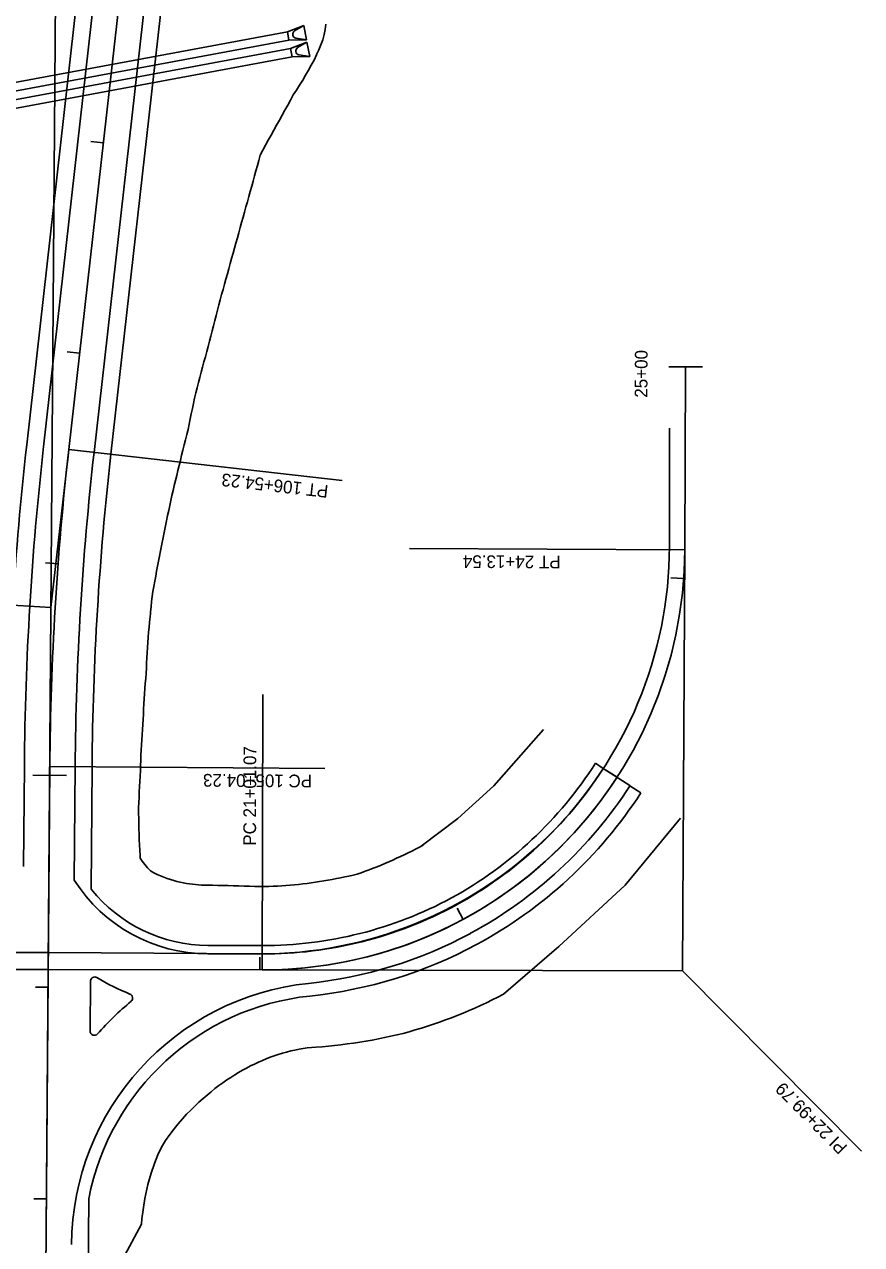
# Model space of a CAD drawing. Extents: x 1311167 to 1314552, y 2087587 to 2090602.
# Drawn here: x 1313980 to 1314376, y 2088279 to 2088855 of the extents above; entities that cross this region are included whole.
import ezdxf

# ---------------------------------------------------------------- set-up
doc = ezdxf.new("R2010")
doc.units = 0
for name, color, linetype in [('R_Bridge', 7, 'Continuous'), ('R_Guardrail', 7, 'Continuous'), ('R_Horz Alg Stationing', 7, 'Continuous'), ('R_Proposed Road', 7, 'Continuous'), ('R_Shld_GR', 7, 'Continuous'), ('R_Shoulder', 7, 'Continuous'), ('S_EDGE_BITUMINOUS', 7, 'Continuous'), ('S_EDGE_CONCRETE', 7, 'Continuous'), ('S_EDGE_PAVEMENT', 7, 'Continuous'), ('S_PAVEMENT_CROWN', 7, 'Continuous')]:
    doc.layers.add(name, color=color, linetype=linetype)

msp = doc.modelspace()

# ---------------------------------------------------------------- linework, layer by layer
at = {"layer": 'R_Bridge'}
for points in [[(1314011.54, 2088800.1), (1314017.5, 2088799.43)], [(1314000.33, 2088700.73), (1314006.29, 2088700.06)], [(1313990.12, 2088601.03), (1313996.1, 2088600.59)], [(1313984.14, 2088500.75), (1314000.14, 2088500.62)], [(1313985.38, 2088400.73), (1313991.38, 2088400.69)], [(1313984.61, 2088300.74), (1313990.61, 2088300.69)]]:
    msp.add_lwpolyline(points, dxfattribs=at)
at = {"layer": 'R_Guardrail'}
for points in [[(1313992.17, 2088504.92), (1313992.74, 2088579.98), (1314001.16, 2088654.58)], [(1314001.16, 2088654.58), (1314130.34, 2088640)], [(1313992.74, 2088579.98), (1313872.96, 2088587.18)], [(1313992.17, 2088504.92), (1314122.17, 2088503.92)]]:
    msp.add_lwpolyline(points, dxfattribs=at)
at = {"layer": 'R_Horz Alg Stationing'}
for p, q in [((1313988.32, 2088000.7), (1313997.14, 2089155.24)), ((1314284.97, 2088608.82), (1314285.06, 2088664.6)), ((1313889.89, 2088417.38), (1313991.5, 2088416.97)), ((1313991.5, 2088416.97), (1314091.16, 2088416.4))]:
    msp.add_line(p, q, dxfattribs=at)
msp.add_arc((1314092.24, 2088609.13), 192.73, 269.67706, 359.90767, dxfattribs=at)
at = {"layer": 'R_Proposed Road'}
for p, q in [((1314001.16, 2088654.58), (1314052.57, 2089110.2)), ((1314001.16, 2088654.58), (1314052.57, 2089110.2)), ((1314001.16, 2088654.58), (1314052.57, 2089110.2)), ((1314292.21, 2088607.13), (1314292.63, 2088693.59)), ((1314292.21, 2088607.13), (1314292.63, 2088693.59)), ((1313988.32, 2088000.7), (1313992.17, 2088504.92)), ((1313992.14, 2088501.05), (1313992.17, 2088504.92)), ((1313896.44, 2088409.22), (1313991.44, 2088409.03)), ((1313896.44, 2088409.22), (1313991.44, 2088409.03)), ((1313991.44, 2088409.03), (1314092.51, 2088408.82)), ((1313991.44, 2088409.03), (1314092.51, 2088408.82))]:
    msp.add_line(p, q, dxfattribs=at)
for centre, radius, start, end in [((1315424.52, 2088493.98), 1432.39, 173.5625, 179.5625), ((1315424.52, 2088493.98), 1432.39, 173.5625, 179.5625), ((1315424.52, 2088493.98), 1432.39, 173.5625, 179.5625), ((1314092.92, 2088608.11), 199.29, 269.88333, 359.71667), ((1314092.92, 2088608.11), 199.29, 269.88333, 327.0745)]:
    msp.add_arc(centre, radius, start, end, dxfattribs=at)
at = {"layer": 'R_Shld_GR'}
for points in [[(1314092.51, 2088408.82), (1314291.22, 2088408.42), (1314292.21, 2088607.13)], [(1314292.21, 2088607.13), (1314162.21, 2088607.77)], [(1314092.51, 2088408.82), (1314092.78, 2088538.82)], [(1314291.22, 2088408.42), (1314375.78, 2088323.27)]]:
    msp.add_lwpolyline(points, dxfattribs=at)
at = {"layer": 'R_Shoulder'}
for points in [[(1314284.63, 2088693.63), (1314300.63, 2088693.55)], [(1314285.7, 2088594.04), (1314291.68, 2088593.6)], [(1314255.16, 2088503.05), (1314260.2, 2088499.79)], [(1314184.63, 2088437.97), (1314187.47, 2088432.68)], [(1314091.45, 2088414.83), (1314091.44, 2088408.83)]]:
    msp.add_lwpolyline(points, dxfattribs=at)
at = {"layer": 'S_EDGE_BITUMINOUS'}
for p, q in [((1314104.47, 2088851.9), (1314112.23, 2088854.88)), ((1314107.82, 2088852.24), (1314112.23, 2088854.88)), ((1314113.51, 2088847.99), (1314112.23, 2088854.88)), ((1313926.54, 2088818.73), (1314104.47, 2088851.9)), ((1314105.2, 2088847.97), (1314104.47, 2088851.9)), ((1313927.27, 2088814.79), (1314105.2, 2088847.97)), ((1313928, 2088810.86), (1314105.94, 2088844.04)), ((1314105.2, 2088847.97), (1314113.51, 2088847.99)), ((1314105.94, 2088844.04), (1314113.69, 2088847.01)), ((1314106.67, 2088840.11), (1314105.94, 2088844.04)), ((1314108.46, 2088848.86), (1314113.51, 2088847.99)), ((1314109.29, 2088844.38), (1314113.69, 2088847.01)), ((1314114.98, 2088840.13), (1314113.69, 2088847.01)), ((1313928.74, 2088806.93), (1314106.67, 2088840.11)), ((1314106.67, 2088840.11), (1314114.98, 2088840.13)), ((1314109.92, 2088841), (1314114.98, 2088840.13))]:
    msp.add_line(p, q, dxfattribs=at)
for centre in [(1314108.77, 2088850.67), (1314110.24, 2088842.81)]:
    msp.add_arc(centre, 1.83, 120.88099, 260.24384, dxfattribs=at)
at = {"layer": 'S_EDGE_CONCRETE'}
msp.add_line((1314035.5, 2088288.69), (1314027.56, 2088274.13), dxfattribs=at)
for points in [[(1314122.61, 2088855.5), (1314122.36, 2088853.01), (1314121.75, 2088850.56), (1314121.18, 2088848.11), (1314120.21, 2088845.7), (1314119.23, 2088843.3), (1314118.43, 2088841.38), (1314118.23, 2088840.9), (1314117.08, 2088838.51), (1314115.71, 2088836.15), (1314114.38, 2088833.78), (1314113.05, 2088831.42), (1314111.68, 2088829.06), (1314110.19, 2088826.71), (1314108.7, 2088824.36), (1314107.21, 2088822.01), (1314105.9, 2088819.64), (1314104.59, 2088817.28), (1314103.27, 2088814.91), (1314101.96, 2088812.54), (1314100.65, 2088810.17), (1314099.35, 2088807.8), (1314098.04, 2088805.44), (1314096.73, 2088803.07), (1314095.43, 2088800.7), (1314094.29, 2088798.61), (1314094.13, 2088798.33), (1314092.83, 2088795.96), (1314091.65, 2088793.58), (1314090.95, 2088791.14), (1314090.27, 2088788.7), (1314089.6, 2088786.26), (1314088.93, 2088783.82), (1314088.26, 2088781.38), (1314087.58, 2088778.94), (1314086.89, 2088776.5), (1314086.21, 2088774.06), (1314085.54, 2088771.62), (1314084.86, 2088769.18), (1314084.19, 2088766.74), (1314083.52, 2088764.3), (1314082.84, 2088761.87), (1314082.16, 2088759.43), (1314081.49, 2088756.99), (1314080.81, 2088754.55), (1314080.14, 2088752.11), (1314079.46, 2088749.67), (1314078.79, 2088747.23), (1314078.11, 2088744.79), (1314077.43, 2088742.35), (1314076.76, 2088739.91), (1314076.08, 2088737.47), (1314075.41, 2088735.03), (1314074.73, 2088732.59), (1314074.03, 2088730.15), (1314073.33, 2088727.72), (1314072.69, 2088725.27), (1314072.04, 2088722.83), (1314071.4, 2088720.39), (1314070.75, 2088717.94), (1314070.12, 2088715.5), (1314069.48, 2088713.06), (1314068.85, 2088710.61), (1314068.22, 2088708.17), (1314067.58, 2088705.72), (1314066.95, 2088703.28), (1314066.31, 2088700.83), (1314065.68, 2088698.39), (1314065.04, 2088695.95), (1314064.41, 2088693.5), (1314063.77, 2088691.06), (1314063.14, 2088688.61), (1314062.51, 2088686.17), (1314061.87, 2088683.72), (1314061.24, 2088681.28), (1314060.6, 2088678.84), (1314060.05, 2088676.38), (1314059.55, 2088673.92), (1314059.05, 2088671.46), (1314058.55, 2088669), (1314058.05, 2088666.54), (1314057.5, 2088664.09), (1314056.87, 2088661.65), (1314056.24, 2088659.2), (1314055.62, 2088656.75), (1314055.04, 2088654.3), (1314054.45, 2088651.85), (1314053.87, 2088649.4), (1314053.3, 2088647.02), (1314052.74, 2088644.66), (1314052.18, 2088642.29), (1314051.59, 2088639.93), (1314051.01, 2088637.57), (1314050.45, 2088635.21), (1314049.92, 2088632.84), (1314049.4, 2088630.47), (1314048.88, 2088628.09), (1314048.36, 2088625.72), (1314047.86, 2088623.34), (1314047.35, 2088620.97), (1314046.86, 2088618.59), (1314046.36, 2088616.21), (1314045.88, 2088613.83), (1314045.4, 2088611.44), (1314044.92, 2088609.06), (1314044.45, 2088606.67), (1314043.99, 2088604.28), (1314043.53, 2088601.9), (1314043.08, 2088599.51), (1314042.63, 2088597.11), (1314042.22, 2088594.72), (1314041.78, 2088592.33), (1314041.34, 2088589.93), (1314040.9, 2088587.53), (1314040.58, 2088585.13), (1314040.31, 2088582.72), (1314040.04, 2088580.31), (1314039.78, 2088577.9), (1314039.7, 2088577.16), (1314039.54, 2088575.49), (1314039.31, 2088573.08), (1314039.09, 2088570.67), (1314038.87, 2088568.25), (1314038.68, 2088565.84), (1314038.52, 2088563.42), (1314038.37, 2088561), (1314038.22, 2088558.59), (1314038.08, 2088556.17), (1314037.94, 2088553.75), (1314037.8, 2088551.33), (1314037.67, 2088548.91), (1314037.49, 2088546.49), (1314037.3, 2088544.08), (1314037.12, 2088541.66), (1314036.94, 2088539.24), (1314036.76, 2088536.82), (1314036.64, 2088534.4), (1314036.52, 2088531.98), (1314036.41, 2088529.56), (1314036.31, 2088527.14), (1314036.18, 2088524.72), (1314036.02, 2088522.29), (1314035.86, 2088519.87), (1314035.71, 2088517.45), (1314035.56, 2088515.03), (1314035.41, 2088512.61), (1314035.27, 2088510.18), (1314035.15, 2088507.76), (1314035.07, 2088505.33), (1314035, 2088502.86), (1314034.87, 2088500.36), (1314034.73, 2088497.86), (1314034.6, 2088495.36), (1314034.46, 2088492.86), (1314034.33, 2088490.36), (1314034.2, 2088487.86), (1314034.07, 2088485.36)], [(1314167.68, 2088467.3), (1314185.05, 2088480.27), (1314202.04, 2088495.78), (1314225.41, 2088522.31)], [(1314034.89, 2088461.56), (1314034.8, 2088462.86), (1314034.69, 2088465.36), (1314034.58, 2088467.86), (1314034.47, 2088470.36), (1314034.36, 2088472.86), (1314034.28, 2088475.36), (1314034.27, 2088477.86), (1314034.24, 2088480.36), (1314034.12, 2088482.86), (1314034.07, 2088485.36)], [(1314290.13, 2088480.41), (1314264.03, 2088448.82), (1314232.76, 2088419.88), (1314206.53, 2088397.34)], [(1314039.74, 2088455.67), (1314041.35, 2088454.73), (1314042.97, 2088453.93), (1314044.56, 2088453.2), (1314046.13, 2088452.55), (1314047.69, 2088451.97), (1314049.22, 2088451.45), (1314050.74, 2088450.98), (1314052.25, 2088450.58), (1314053.74, 2088450.23), (1314055.23, 2088449.93), (1314056.7, 2088449.69), (1314058.15, 2088449.45), (1314059.59, 2088449.26), (1314061.03, 2088449.12), (1314062.46, 2088448.98), (1314063.88, 2088448.88), (1314065.3, 2088448.81), (1314066.72, 2088448.8), (1314069.02, 2088448.76), (1314071.52, 2088448.7), (1314074.02, 2088448.64), (1314076.52, 2088448.67), (1314079.02, 2088448.59), (1314081.52, 2088448.5), (1314084.02, 2088448.41), (1314086.52, 2088448.32), (1314089.02, 2088448.22), (1314091.52, 2088448.16), (1314093.74, 2088448.19), (1314095.74, 2088448.25), (1314097.75, 2088448.33), (1314099.75, 2088448.42), (1314101.75, 2088448.53), (1314103.75, 2088448.67), (1314105.75, 2088448.82), (1314107.75, 2088448.99), (1314109.74, 2088449.18), (1314111.74, 2088449.39), (1314113.73, 2088449.63), (1314115.71, 2088449.92), (1314117.7, 2088450.22), (1314119.68, 2088450.54), (1314121.66, 2088450.85), (1314123.63, 2088451.19), (1314125.61, 2088451.54), (1314127.58, 2088451.91), (1314129.55, 2088452.3), (1314131.52, 2088452.71), (1314133.49, 2088453.13), (1314135.45, 2088453.58), (1314137.4, 2088454.07), (1314139.31, 2088454.7), (1314141.2, 2088455.38), (1314143.08, 2088456.09), (1314144.96, 2088456.81), (1314146.82, 2088457.56), (1314148.68, 2088458.32), (1314150.53, 2088459.09), (1314152.37, 2088459.89), (1314154.2, 2088460.7), (1314156.02, 2088461.54), (1314157.85, 2088462.36), (1314159.67, 2088463.2), (1314161.48, 2088464.05), (1314163.27, 2088464.94), (1314165.04, 2088465.87), (1314166.81, 2088466.82), (1314168.56, 2088467.78)], [(1314034.89, 2088461.56), (1314035.84, 2088460.2), (1314037.11, 2088458.57), (1314038.38, 2088457.03), (1314039.74, 2088455.67)], [(1314046.85, 2088328.27), (1314048.89, 2088331.11), (1314050.91, 2088333.74), (1314052.91, 2088336.18), (1314054.88, 2088338.47), (1314056.85, 2088340.6), (1314058.81, 2088342.61), (1314060.74, 2088344.52), (1314062.66, 2088346.33), (1314064.57, 2088348.05), (1314066.46, 2088349.68), (1314068.35, 2088351.24), (1314070.23, 2088352.73), (1314072.09, 2088354.16), (1314073.96, 2088355.52), (1314075.83, 2088356.82), (1314077.69, 2088358.06), (1314079.55, 2088359.24), (1314081.41, 2088360.37), (1314083.28, 2088361.44), (1314085.14, 2088362.46), (1314087.01, 2088363.43), (1314088.87, 2088364.35), (1314090.74, 2088365.24), (1314092.61, 2088366.07), (1314094.48, 2088366.85), (1314096.36, 2088367.57), (1314098.24, 2088368.25), (1314100.13, 2088368.88), (1314102.07, 2088369.48), (1314104.05, 2088370.03), (1314106.02, 2088370.53), (1314107.98, 2088370.98), (1314109.94, 2088371.36), (1314111.9, 2088371.68), (1314113.86, 2088371.94), (1314115.82, 2088372.15), (1314117.88, 2088372.31), (1314120.85, 2088372.53), (1314123.82, 2088372.8), (1314126.78, 2088373.11), (1314129.74, 2088373.46), (1314132.7, 2088373.82), (1314135.66, 2088374.23), (1314138.61, 2088374.67), (1314141.56, 2088375.15), (1314144.5, 2088375.69), (1314147.43, 2088376.25), (1314150.37, 2088376.84), (1314153.29, 2088377.47), (1314156.21, 2088378.14), (1314159.12, 2088378.85), (1314162.01, 2088379.64), (1314164.88, 2088380.47), (1314167.75, 2088381.33), (1314170.61, 2088382.24), (1314173.46, 2088383.17), (1314176.29, 2088384.15), (1314179.12, 2088385.16), (1314181.92, 2088386.21), (1314184.72, 2088387.3), (1314187.5, 2088388.42), (1314190.27, 2088389.58), (1314193.02, 2088390.78), (1314195.75, 2088392.02), (1314198.47, 2088393.3), (1314201.17, 2088394.61), (1314203.86, 2088395.95), (1314206.53, 2088397.34)], [(1314035.5, 2088288.69), (1314035.67, 2088291.28), (1314037.07, 2088300.9), (1314038.48, 2088307.51), (1314040.04, 2088312.83), (1314041.58, 2088317.41), (1314043.25, 2088321.43), (1314044.97, 2088325.05), (1314046.85, 2088328.27)]]:
    msp.add_lwpolyline(points, dxfattribs=at)
at = {"layer": 'S_EDGE_PAVEMENT'}
for p, q in [((1313981.29, 2088656.82), (1314032.69, 2089112.44)), ((1314021.03, 2088652.34), (1314072.44, 2089107.95)), ((1314011.73, 2088446.9), (1314012.17, 2088504.76)), ((1314250.01, 2088506.39), (1314253.73, 2088503.98)), ((1314266.33, 2088495.82), (1314271.49, 2088492.48)), ((1314066.93, 2088420.38), (1314092.54, 2088420.32)), ((1314009.96, 2088215.54), (1314010.61, 2088300.74))]:
    msp.add_line(p, q, dxfattribs=at)
for centre, radius, start, end in [((1315424.52, 2088493.98), 1452.39, 173.5625, 179.5625), ((1315424.52, 2088493.98), 1412.39, 173.5625, 179.5625), ((1314091.75, 2088607.48), 187.79, 298.73164, 327.43214), ((1314092.84, 2088608.07), 212.79, 298.34924, 327.09619), ((1314067.07, 2088491.38), 71, 218.78938, 269.88333), ((1314092.92, 2088608.11), 187.79, 269.88333, 298.3245), ((1314092.92, 2088608.11), 212.79, 275.97277, 298.3245), ((1314127.44, 2088278.12), 119, 95.97277, 169.04314)]:
    msp.add_arc(centre, radius, start, end, dxfattribs=at)
at = {"layer": 'S_PAVEMENT_CROWN'}
for p, q in [((1313989.24, 2088655.92), (1314040.64, 2089111.54)), ((1313989.24, 2088655.92), (1314040.64, 2089111.54)), ((1314013.09, 2088653.23), (1314064.49, 2089108.85)), ((1314013.09, 2088653.23), (1314064.49, 2089108.85)), ((1313979.81, 2088457.6), (1313980.17, 2088505.01)), ((1314003.76, 2088451.16), (1314004.17, 2088504.83)), ((1314253.73, 2088503.98), (1314266.32, 2088495.83)), ((1314066.92, 2088416.38), (1314092.53, 2088416.32)), ((1314011.22, 2088379.93), (1314011.4, 2088403.48))]:
    msp.add_line(p, q, dxfattribs=at)
for centre, radius, start, end in [((1315424.52, 2088493.98), 1444.39, 173.5625, 179.5625), ((1315424.52, 2088493.98), 1444.39, 173.5625, 179.5625), ((1315424.52, 2088493.98), 1420.39, 173.5625, 179.5625), ((1315424.52, 2088493.98), 1420.39, 173.5625, 179.5625), ((1314092.56, 2088607.92), 191.79, 298.44752, 327.19752), ((1314092.56, 2088607.92), 206.79, 298.43857, 327.18857), ((1314067.07, 2088491.38), 75, 212.42238, 269.88333), ((1314092.92, 2088608.11), 191.79, 269.88333, 298.3245), ((1314092.92, 2088608.11), 206.79, 275.97277, 298.3245), ((1314013.4, 2088403.47), 2, 58.59424, 179.5625), ((1314067.07, 2088491.38), 101, 238.59424, 248.5128), ((1314127.44, 2088278.12), 125, 95.97277, 179.5625), ((1314127.44, 2088278.12), 151, 129.88041, 138.29462), ((1314029.34, 2088395.53), 2, 309.88041, 68.5128), ((1314013.22, 2088379.92), 2, 179.5625, 318.29462)]:
    msp.add_arc(centre, radius, start, end, dxfattribs=at)

# ---------------------------------------------------------------- texts
at = {"layer": 'R_Guardrail'}
for s, rotation, p in [('PT 106+54.23', 173.5625, (1314124.04, 2088637.69)), ('PC 105+04.23', 179.5625, (1314116.14, 2088500.97))]:
    msp.add_text(s, height=6, rotation=rotation, dxfattribs=at).set_placement(p)
at = {"layer": 'R_Shld_GR'}
for s, rotation, p in [('PT 24+13.54', 179.71667, (1314233.56, 2088604.42)), ('PC 21+01.07', 89.88333, (1314089.63, 2088467.43)), ('PI 22+99.79', 134.8, (1314369.42, 2088325.41))]:
    msp.add_text(s, height=6, rotation=rotation, dxfattribs=at).set_placement(p)
at = {"layer": 'R_Shoulder'}
msp.add_text('25+00', height=6, rotation=89.71667, dxfattribs=at).set_placement((1314274.56, 2088679.03))

doc.saveas('drawing.dxf')
